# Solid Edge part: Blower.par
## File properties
Author: CADCIM
Template: NORMENG.PAR
Last saved by: CADCIM
Revision: 6
Application: Solid Edge
Density: 0 lbm/in^3
Accuracy: 0.99
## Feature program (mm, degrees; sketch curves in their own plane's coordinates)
sketch for "unnamed RevolvedProtrusion 1" #1 plane through (0, 0, 0) normal (0, -1, 0) x-axis (1, 0, 0)
  line (0, 171.45) -> (139.7, 171.45)
  line (139.7, 171.45) -> (139.7, 165.1)
  line (139.7, 165.1) -> (0, 165.1)
  line (0, 165.1) -> (0, 171.45)
sketch for "unnamed RevolvedProtrusion 1" #2 plane through (0, 0, 0) normal (0, -1, 0) x-axis (1, 0, 0)
  line (0, 0) -> (0, 0)
  line (0, 0) -> (0, 0)
  line (139.7, 0) -> (139.7, -12.7)
  line (139.7, -12.7) -> (38.1, -12.7)
  line (38.1, -12.7) -> (38.1, -76.2)
  line (38.1, -76.2) -> (0, -76.2)
  line (0, -76.2) -> (0, 0)
  line (0, 0) -> (139.7, 0)
  dimension (linear) = 38.1
  dimension (linear) = 139.7
revolve "unnamed RevolvedProtrusion 1" add finite 360 deg
sketch for "unnamed Protrusion 1" plane through (0, 0, 0) normal (0, 0, 1) x-axis (1, 0, 0)
  line (76.708, 0) -> (139.7, 0)
  line (127.6948, -46.4771) -> (131.2751, -47.7802)
  line (76.708, -6.35) -> (135.0219, -6.35)
  line (76.708, 0) -> (76.708, -6.35)
  dimension (linear) = 127.6948
  dimension (linear) = 76.708
extrude "unnamed Protrusion 1" add through along +normal
pattern "unnamed Pattern 1" of "unnamed Protrusion 1"
extrude "unnamed Protrusion 2" add through
extrude "unnamed Protrusion 3" add through
extrude "unnamed Protrusion 4" add through
extrude "unnamed Protrusion 5" add through
extrude "unnamed Protrusion 6" add through
sketch for "unnamed Hole 1" plane through (0, 0, -76.2) normal (0, 0, -1) x-axis (1, 0, 0)
hole "unnamed Hole 1" through
sketch for "ExtrudedCutout_1" plane through (0, 0, 171.45) normal (0, 0, 1) x-axis (0, -1, 0)
extrude "ExtrudedCutout_1" cut finite 6.35 along -normal
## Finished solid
Body 1: solid body, 50 faces, 139 edges, 84 vertices.
  Faces by surface: plane 40, cylinder 10
  Edges by curve: line 96, circle 43
Bounding box of the edges (mm): 279.400 x 279.400 x 247.650, from (-139.7, -139.7, -76.2) to (139.7, 139.7, 171.45).
Cylindrical faces by radius (mm): R19.05 x1, R38.1 x1, R101.6 x1, R131.6115 x6, R139.7 x1
Planar faces by outward normal: +x 1, +y 2, +z 8, -x 1, -y 2, -z 8, oblique 18
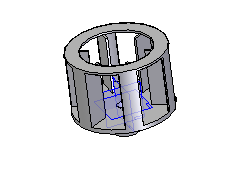
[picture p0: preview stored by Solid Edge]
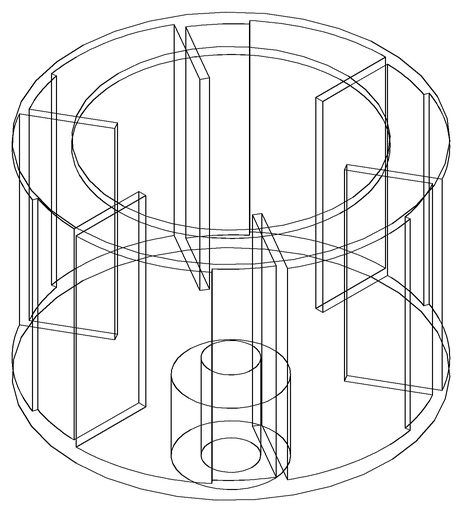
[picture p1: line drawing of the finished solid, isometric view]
